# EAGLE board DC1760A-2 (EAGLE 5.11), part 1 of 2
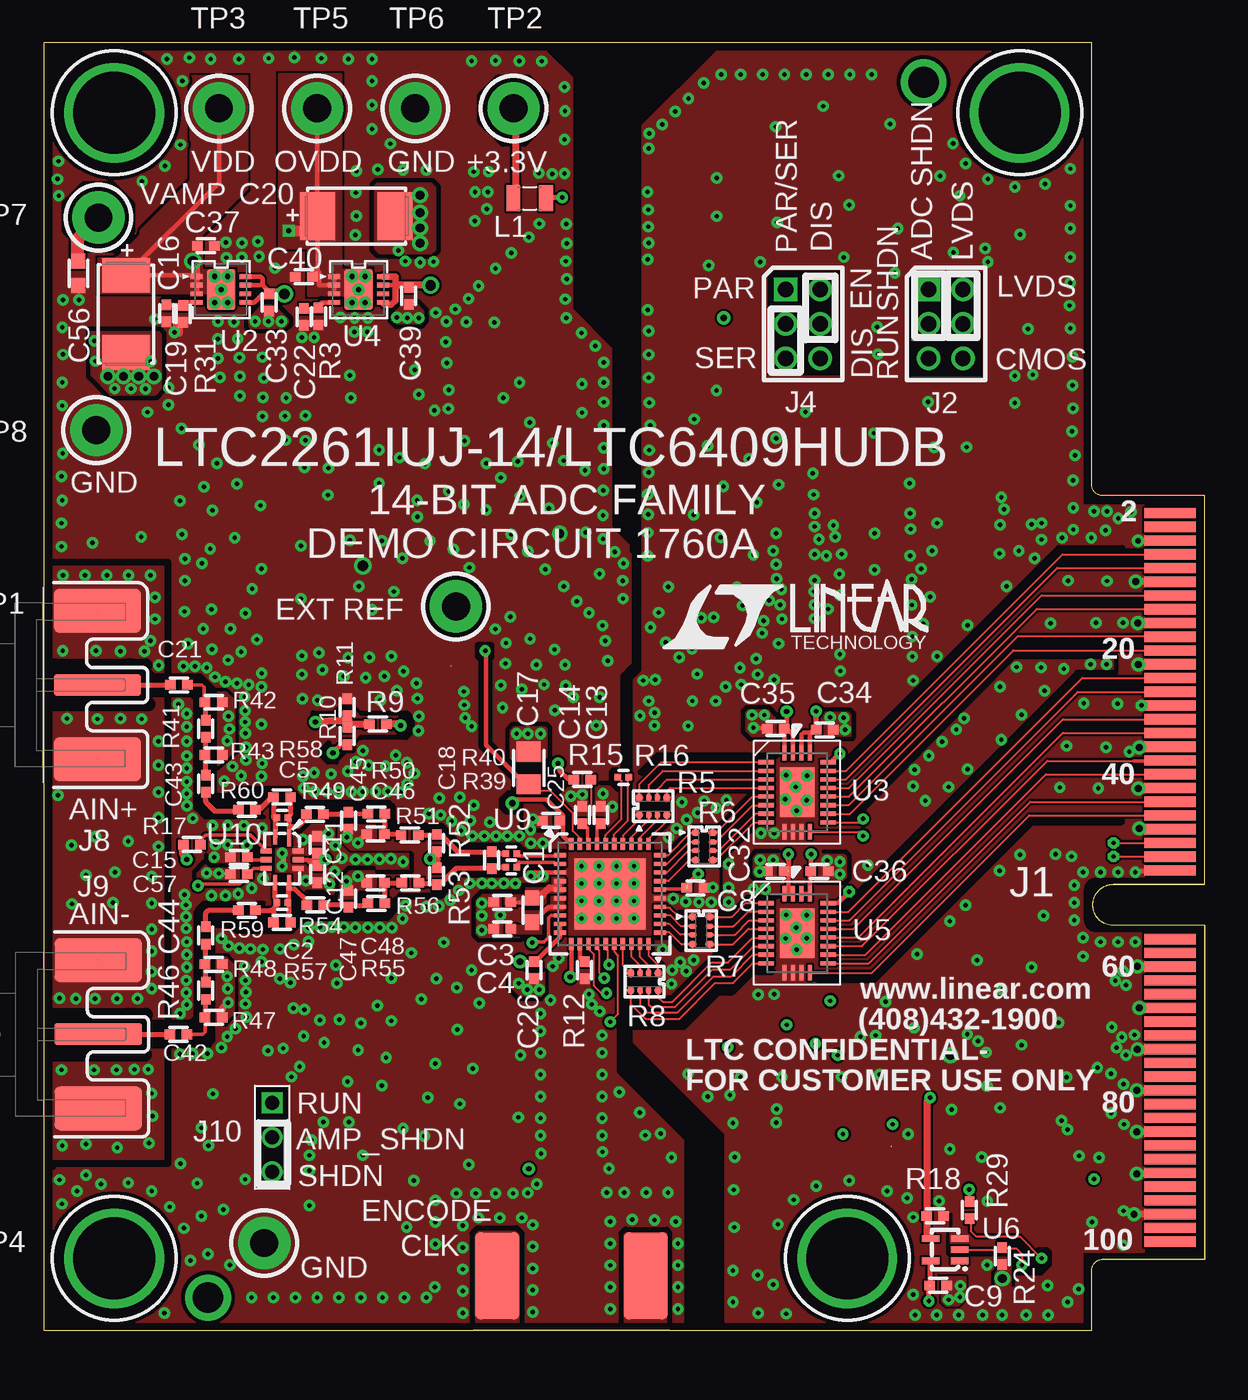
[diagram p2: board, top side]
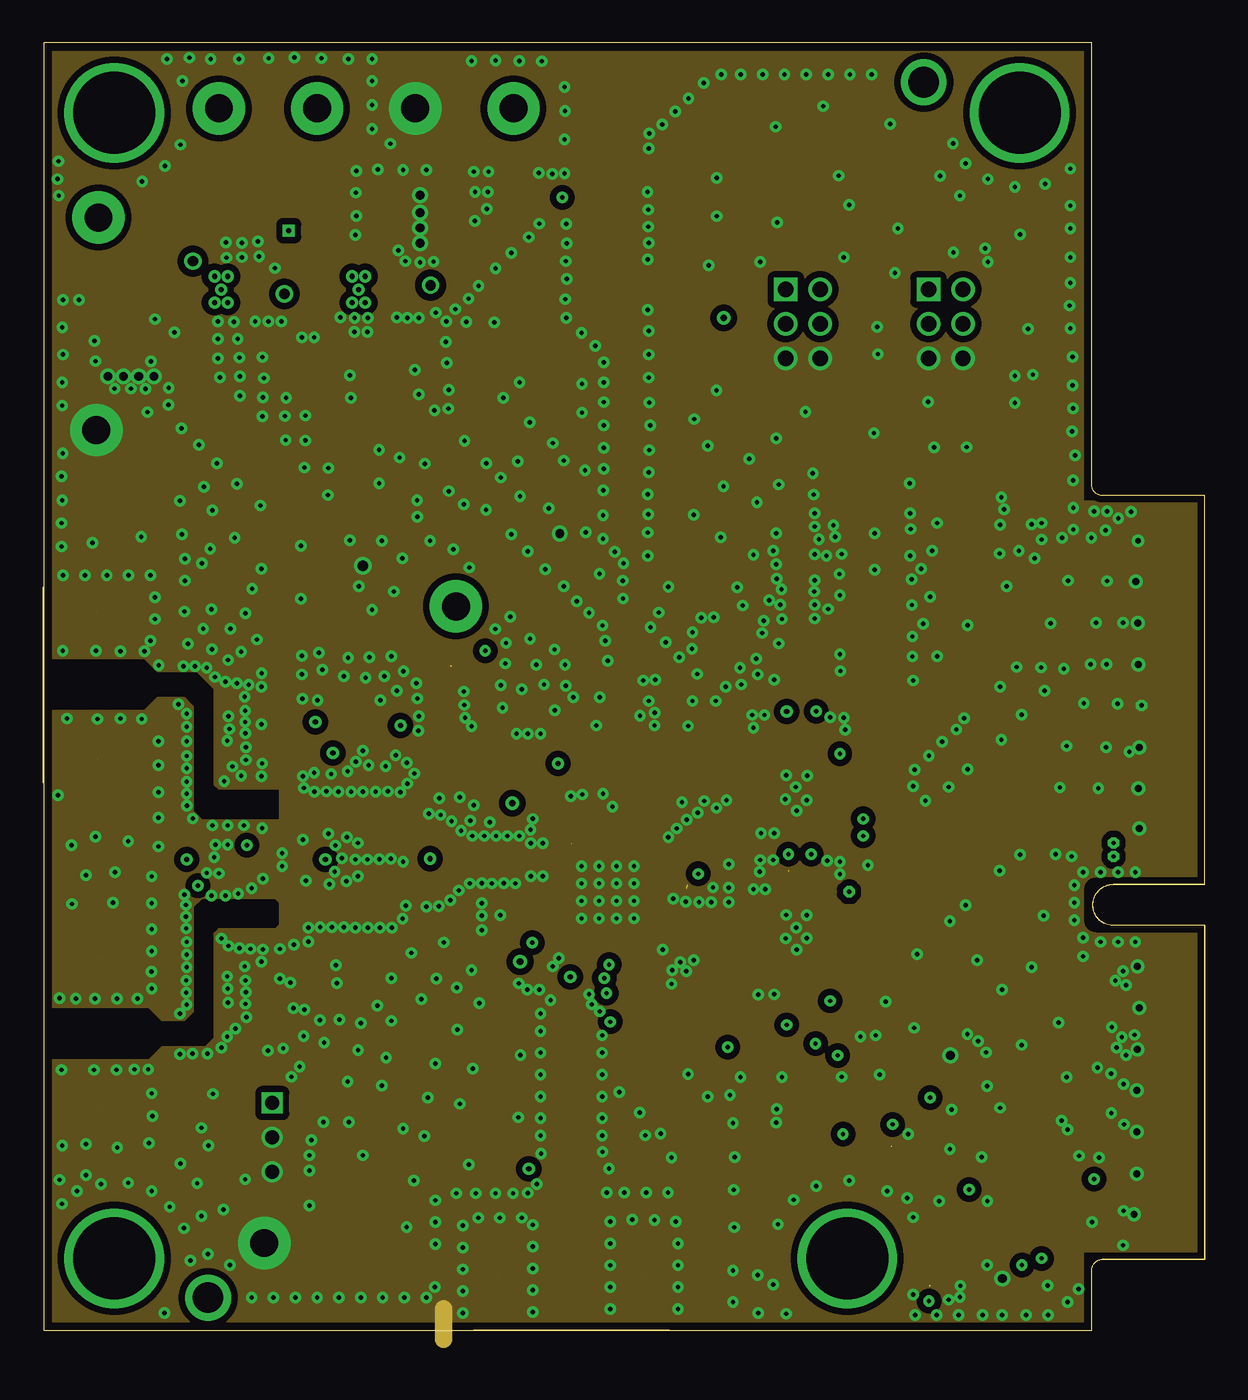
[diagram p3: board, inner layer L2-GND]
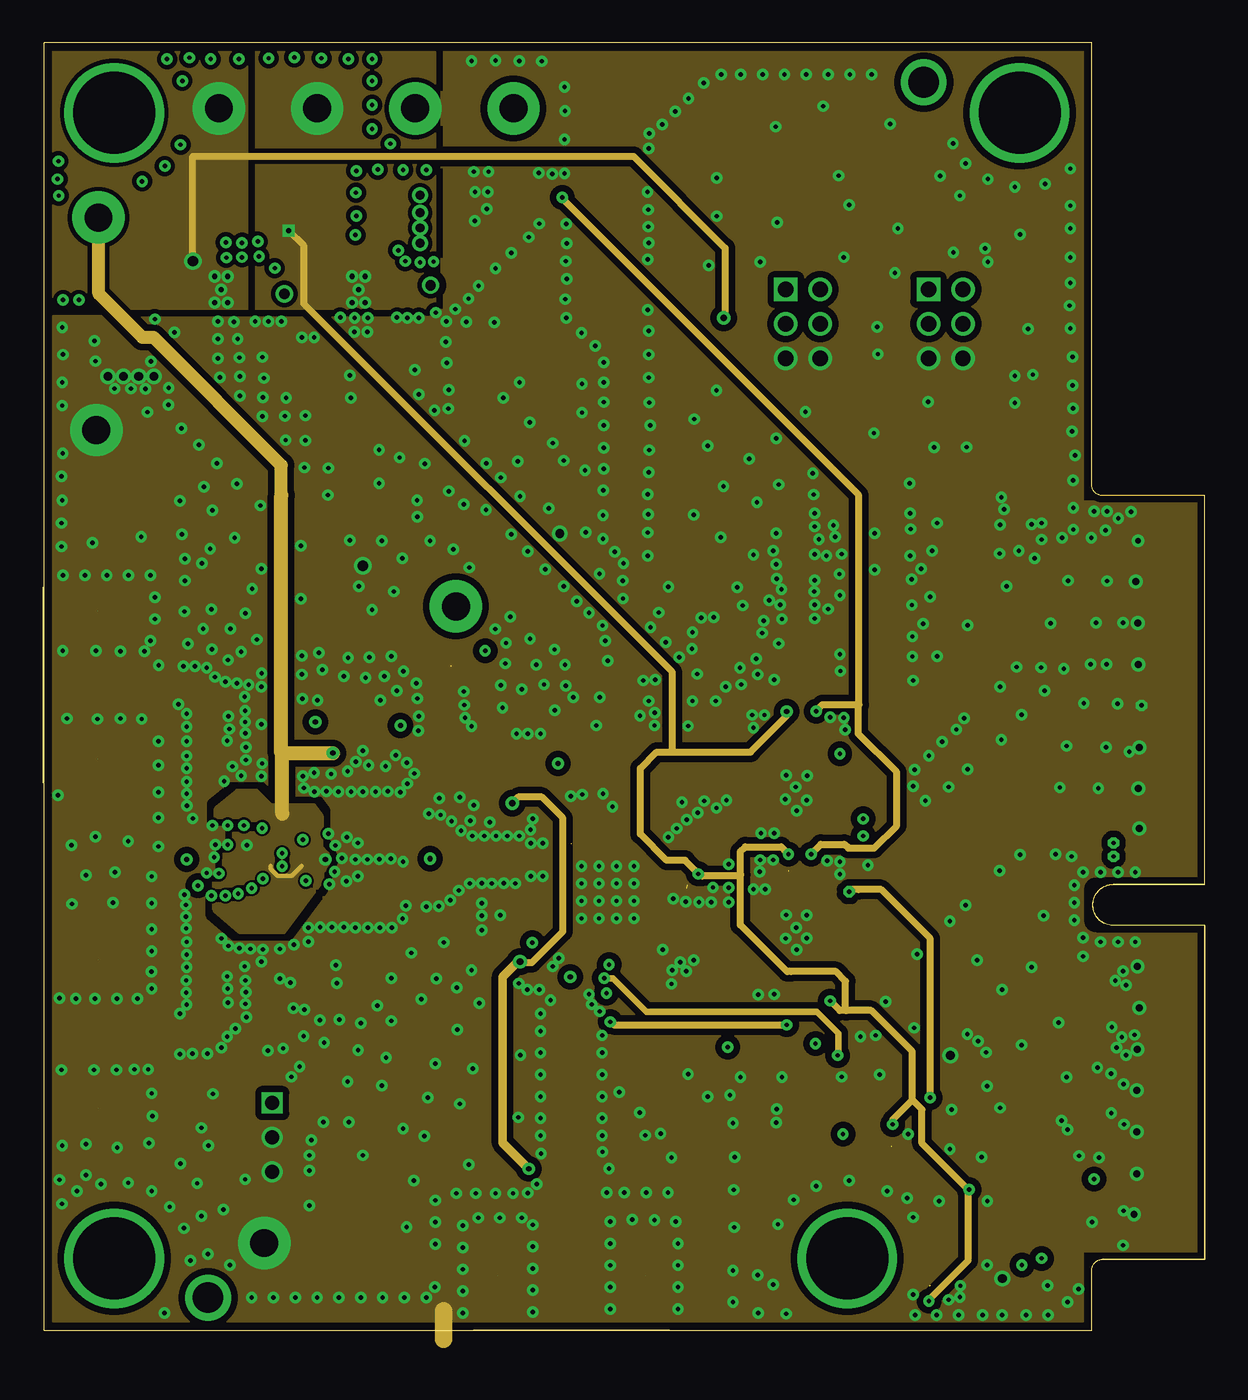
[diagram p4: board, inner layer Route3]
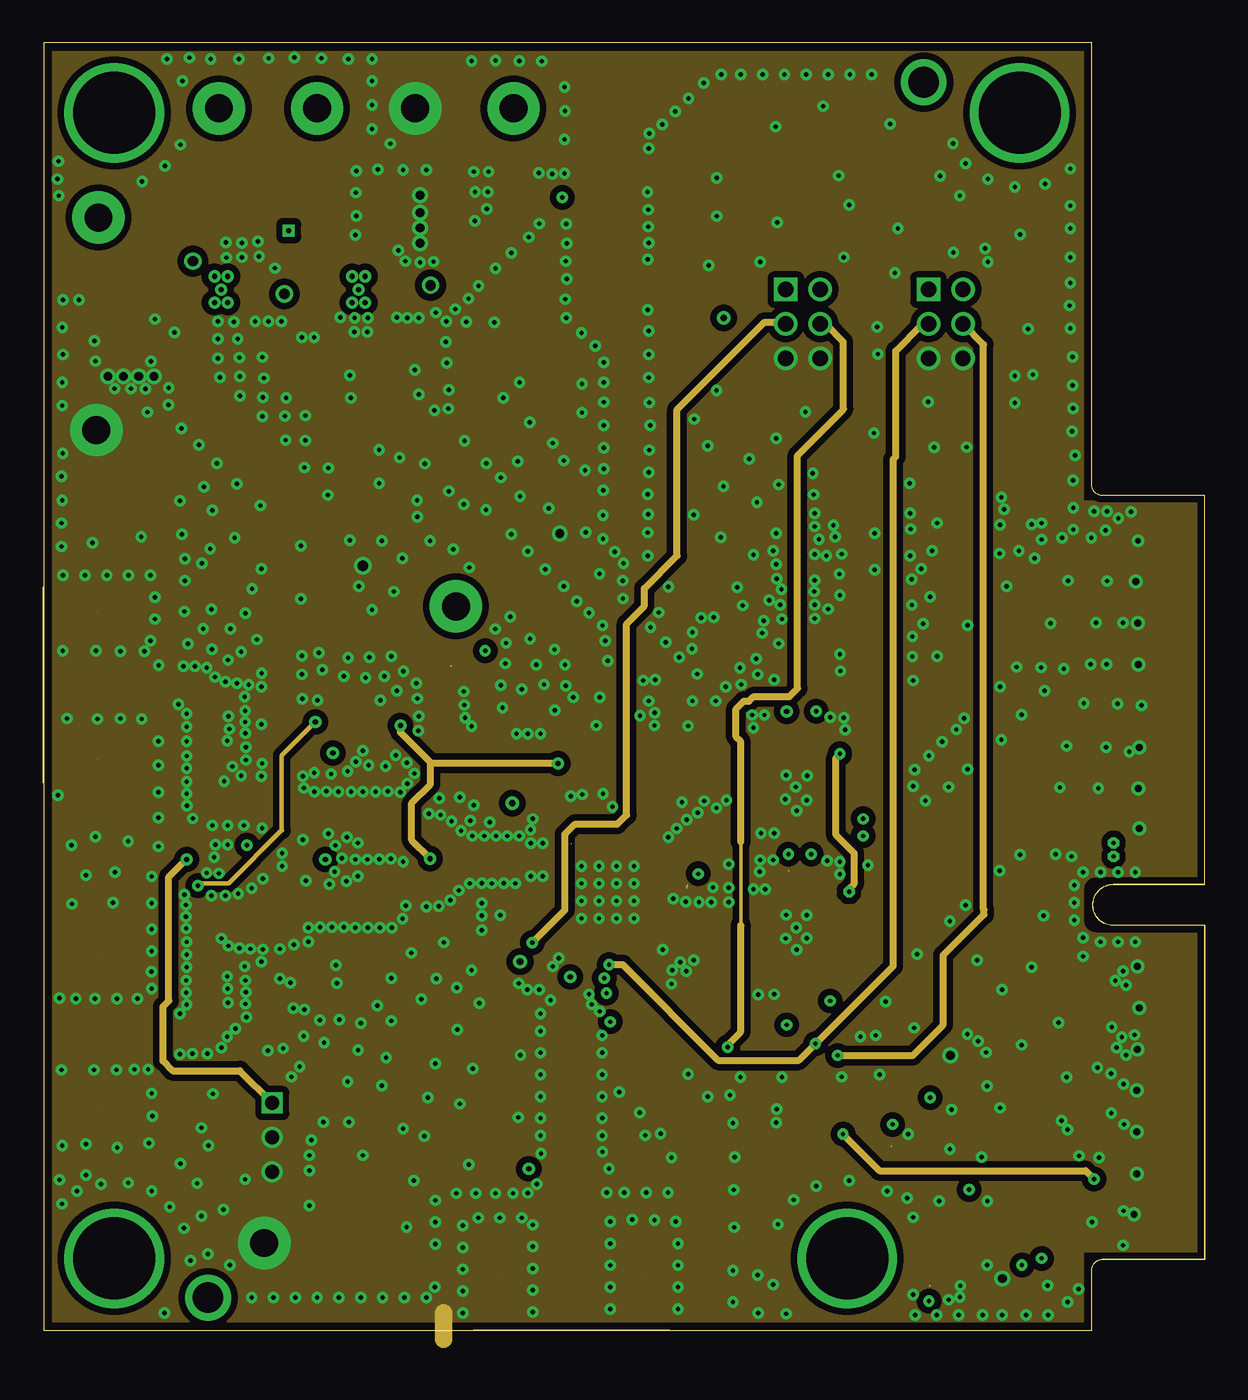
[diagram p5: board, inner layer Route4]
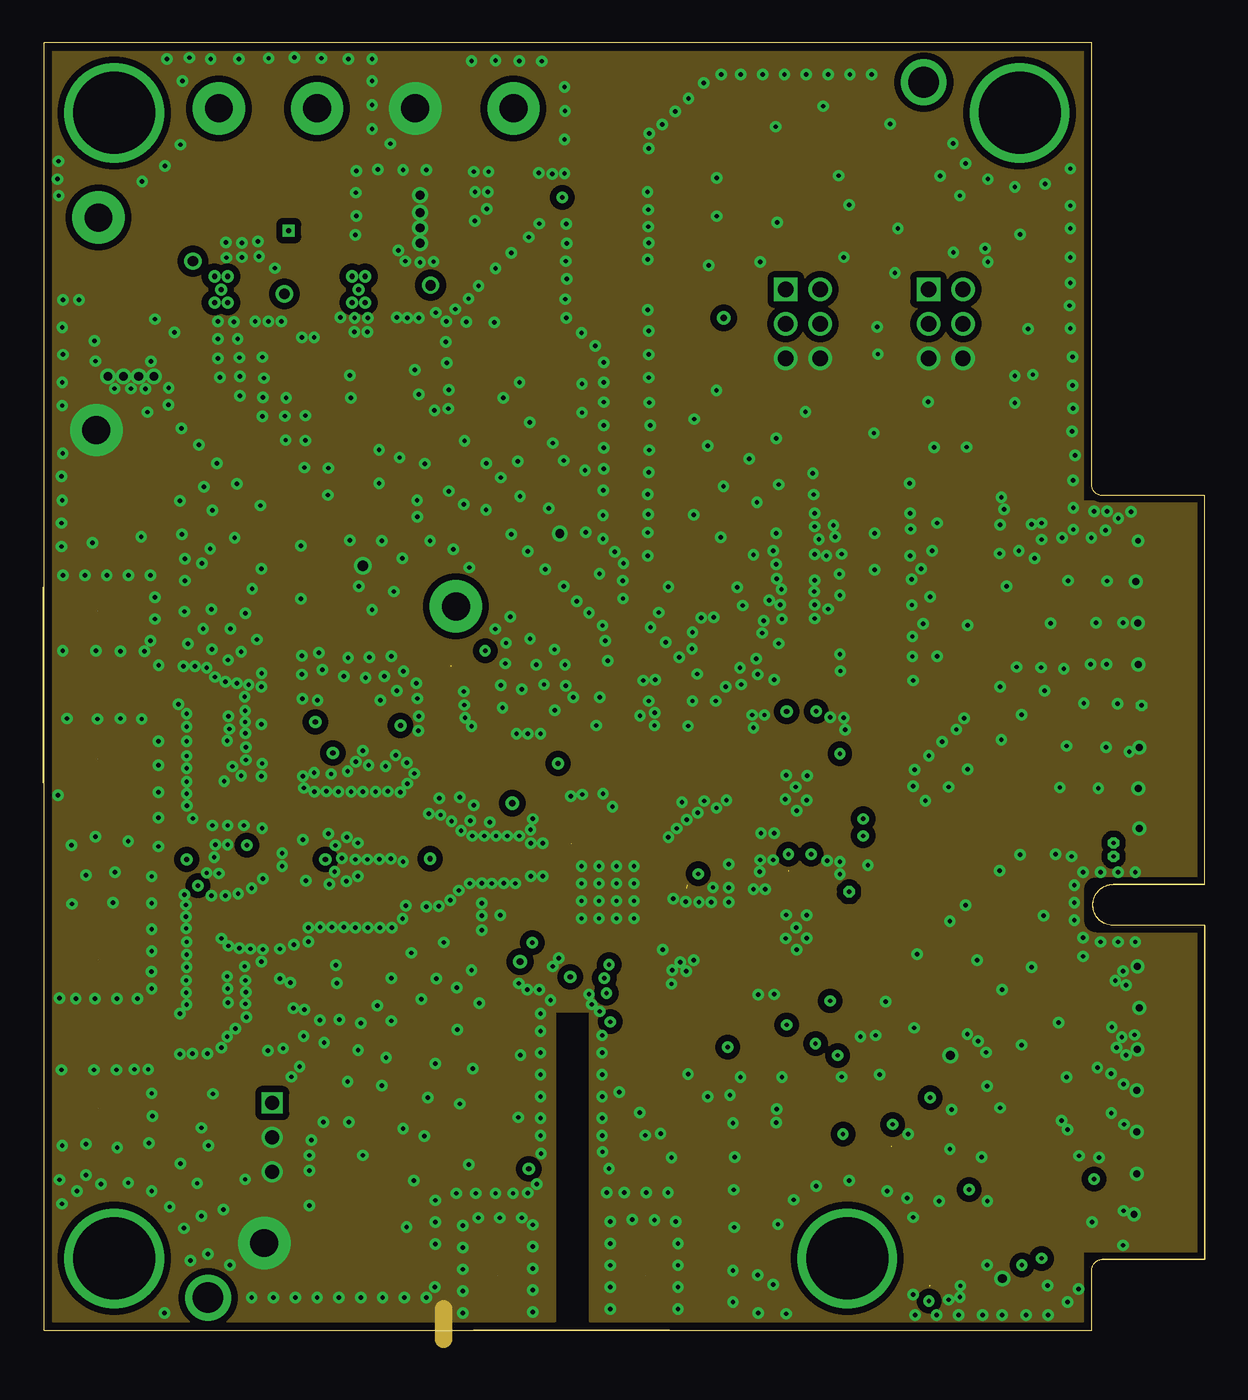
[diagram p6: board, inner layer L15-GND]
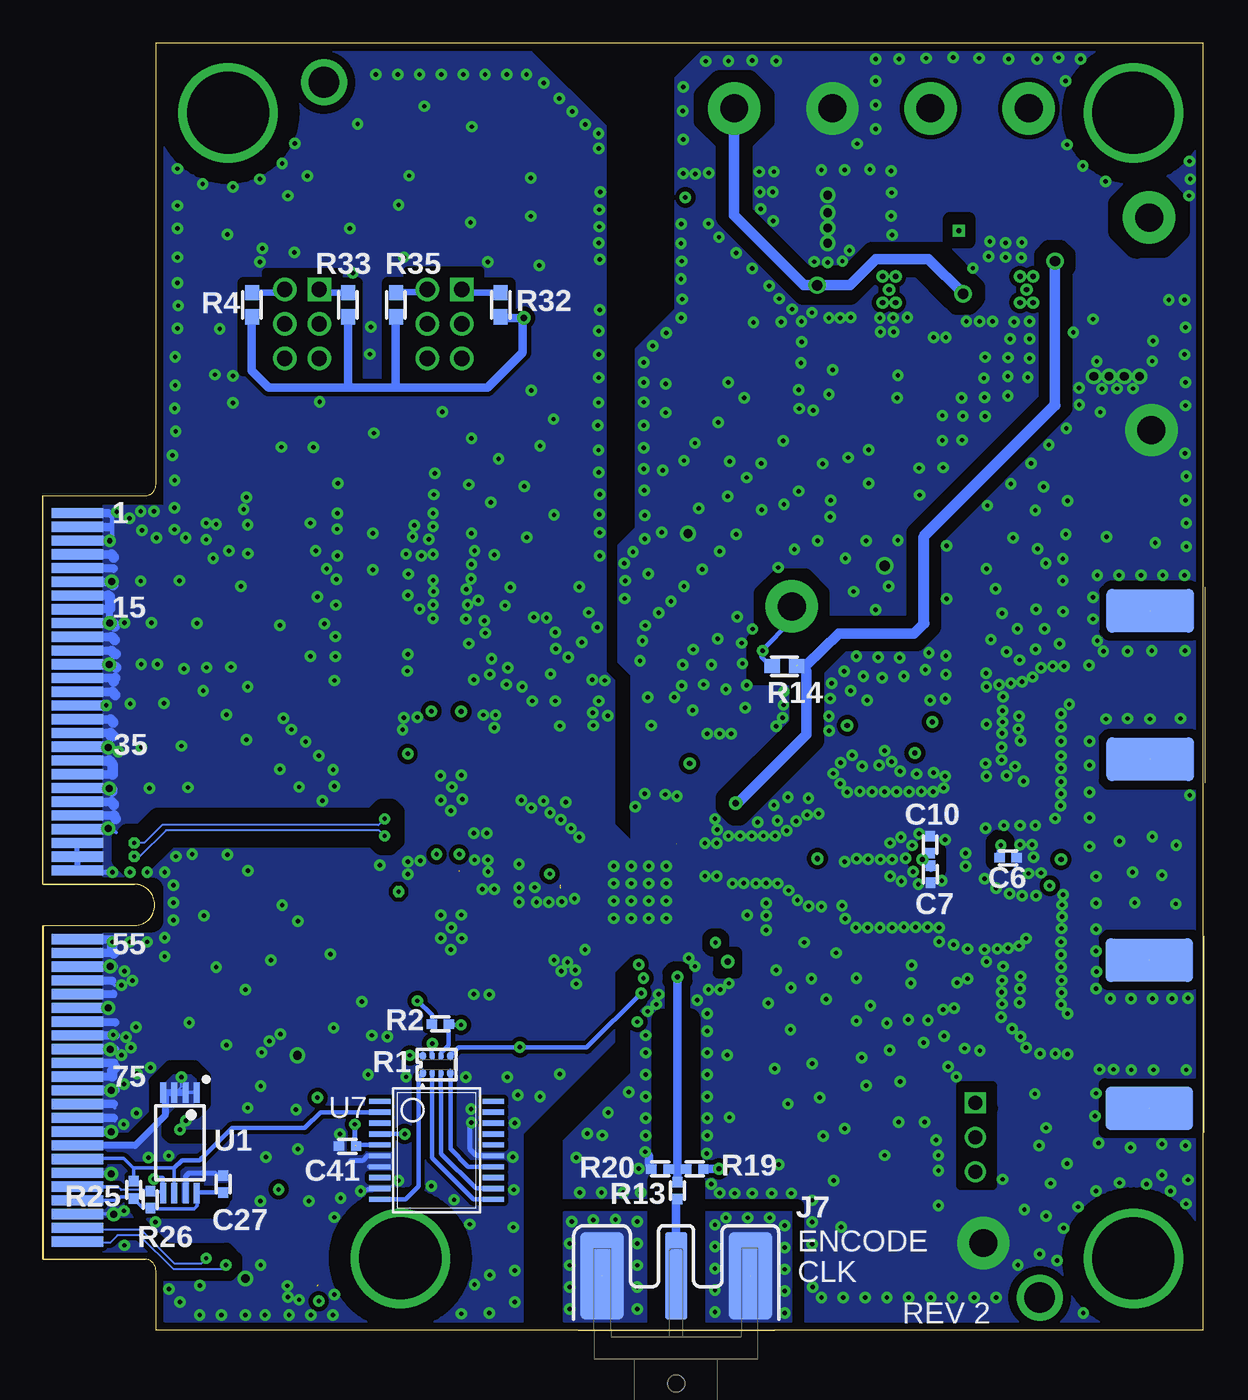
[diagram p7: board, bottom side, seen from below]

Size 67.62 x 74.93 mm. Coordinates in mm from the lower left corner, seen from the top.
Outline: 61.04,0 0.08,0 0.08,74.93 61.04,74.93 61.04,49.22 arc90 61.67,48.59 67.62,48.59 67.62,25.96 62.29,25.96 arc90 61.12,24.79 61.12,24.73 arc90 62.27,23.57 67.62,23.57 67.62,4.14 61.71,4.14 arc90 61.04,3.48 61.04,0
Copper layers (1*2+3*4+15*16): Top 0.0508mm / dielectric 0.4318mm / L2-GND 0.0254mm / dielectric 0.7112mm / Route3 0.0254mm / dielectric 0.3048mm / Route4 0.0254mm / dielectric 0.7112mm / L15-GND 0.0254mm / dielectric 0.4318mm / Bottom 0.0508mm
Design rules "Kim-Design Rules": minimum track width 5mil, minimum drill 10mil, track to track 5mil, track to pad 5mil, pad to pad 5mil, via to via 5mil, smd to smd 0mil, copper to edge 10mil, drill to drill 10mil, minimum pad ring 8mil, minimum via ring 8mil, stop-mask expansion 4mil, vias tented up to drill 15mil, thermal gap 10mil
Holes 0.25 mm at 121.98,32.81
Holes 0.3 mm at 121.98,37.89
Holes 0.38 mm at 121.98,42.97
Holes 0.41 mm at 121.98,48.05
Holes 0.51 mm at 121.98,53.13
Holes 0.61 mm at 121.98,58.21
Holes 0.81 mm at 121.98,63.29
Holes 0.89 mm at 121.98,68.37
Holes 1.63 mm at 121.98,73.45
Holes 1.78 mm at 121.98,78.53
Holes 4.78 mm at 121.98,83.61
tRestrict: area 12.3,8.4 to 14.2,14.2; area 50.4,55.5 to 54.7,61.6; area 42.2,55.6 to 46.4,61.7; area 8.2,0.5 to 11,3.3; area 49.8,71.2 to 52.7,74.1; 341 lines
bRestrict: area 12.3,8.4 to 14.2,14.2; area 42.2,55.6 to 46.4,61.7; area 50.4,55.5 to 54.6,61.6; area 8.2,0.5 to 11,3.3; area 49.8,71.2 to 52.7,74.1; 221 lines

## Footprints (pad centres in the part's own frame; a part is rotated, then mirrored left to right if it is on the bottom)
0603 = smd 0.889 x 0.813: 1 -0.71,0; 2 0.71,0
0201 = smd 0.381 x 0.381: 1 -0.32,0; 2 0.32,0
0402 = smd 0.61 x 0.559: 1 -0.498,0; 2 0.498,0
EIA6032-28(C) = smd 2.032 x 2.794: A -2.246,0; K 2.246,0
0805 = smd 1.143 x 1.397: 1 -0.952,0; 2 0.952,0
MEC8-150-02-L-D-EDGE_CONN-NEW-ORIGIN = smd 3 x 0.6 bottom: 1 3.3,22.8; 3 3.3,22; 5 3.3,21.2; 7 3.3,20.4; 9 3.3,19.6; 11 3.3,18.8; 13 3.3,18; 15 3.3,17.2; 17 3.3,16.4; 19 3.3,15.6; 21 3.3,14.8; 23 3.3,14; 25 3.3,13.2; 27 3.3,12.4; 29 3.3,11.6; 31 3.3,10.8; 33 3.3,10; 35 3.3,9.2; 37 3.3,8.4; 39 3.3,7.6; 41 3.3,6.8; 43 3.3,6; 45 3.3,5.2; 47 3.3,4.4; 49 3.3,3.6; 51 3.3,2.8; 53 3.3,2; 55 3.3,-2; 57 3.3,-2.8; 59 3.3,-3.6; 61 3.3,-4.4; 63 3.3,-5.2; 65 3.3,-6; 67 3.3,-6.8; 69 3.3,-7.6; 71 3.3,-8.4; 73 3.3,-9.2; 75 3.3,-10; 77 3.3,-10.8; 79 3.3,-11.6; 81 3.3,-12.4; 83 3.3,-13.2; 85 3.3,-14; 87 3.3,-14.8; 89 3.3,-15.6; 91 3.3,-16.4; 93 3.3,-17.2; 95 3.3,-18; 97 3.3,-18.8; 99 3.3,-19.6 | smd 3 x 0.6: 2 3.3,22.8; 4 3.3,22; 6 3.3,21.2; 8 3.3,20.4; 10 3.3,19.6; 12 3.3,18.8; 14 3.3,18; 16 3.3,17.2; 18 3.3,16.4; 20 3.3,15.6; 22 3.3,14.8; 24 3.3,14; 26 3.3,13.2; 28 3.3,12.4; 30 3.3,11.6; 32 3.3,10.8; 34 3.3,10; 36 3.3,9.2; 38 3.3,8.4; 40 3.3,7.6; 42 3.3,6.8; 44 3.3,6; 46 3.3,5.2; 48 3.3,4.4; 50 3.3,3.6; 52 3.3,2.8; 54 3.3,2; 56 3.3,-2; 58 3.3,-2.8; 60 3.3,-3.6; 62 3.3,-4.4; 64 3.3,-5.2; 66 3.3,-6; 68 3.3,-6.8; 70 3.3,-7.6; 72 3.3,-8.4; 74 3.3,-9.2; 76 3.3,-10; 78 3.3,-10.8; 80 3.3,-11.6; 82 3.3,-12.4; 84 3.3,-13.2; 86 3.3,-14; 88 3.3,-14.8; 90 3.3,-15.6; 92 3.3,-16.4; 94 3.3,-17.2; 96 3.3,-18; 98 3.3,-18.8; 100 3.3,-19.6
HD2X3-079 = drill 0.889 pad 1.372 square: 1 0,0 | drill 0.889 pad 1.372 round: 2 0,2.007; 3 2.007,0; 4 2.007,2.007; 5 4.013,0; 6 4.013,2.007
SMA-EDGE-MNT@2 = smd 5.08 x 1.27: 1 3.175,0 | smd 5.08 x 2.54: 2 3.175,4.318; 3 3.175,-4.318 | smd 5.08 x 2.54 bottom: 4 3.175,4.318; 5 3.175,-4.318
HDR-3X1PS-2MM = drill 0.813 square: 1 0,0 | drill 0.813 round: 2 2,0; 3 4,0
R0805 = smd 0.8 x 1.5: 1 -0.951,0; 2 0.951,0
MTG-8831 = drill 4.775 pad 4.775 round: 1 0,0
MNR04-QUAD-RES-ARRAY = smd 0.4 x 0.5: 1 -0.8,-0.5; 4 0.8,-0.5; 5 0.8,0.5; 8 -0.8,0.5 | smd 0.3 x 0.5: 2 -0.25,-0.5; 3 0.25,-0.5; 6 0.25,0.5; 7 -0.25,0.5
MILLMAX-2308-2 = drill 1.626 pad 3.048 round: 1 0,0
TSSOP8@1 = smd 0.35 x 1.2: 1 -0.975,-2.925; 2 -0.325,-2.925; 3 0.325,-2.925; 4 0.975,-2.925; 5 0.975,2.925; 6 0.325,2.925; 7 -0.325,2.925; 8 -0.975,2.925
DFN-8_3X3MM@1 = smd 0.28 x 0.675: 1 -0.75,-1.425; 2 -0.25,-1.425; 3 0.25,-1.425; 4 0.75,-1.425; 5 0.75,1.425; 6 0.25,1.425; 7 -0.25,1.425; 8 -0.75,1.425 | smd 2.38 x 1.65: USM 0,0
DFN_8X4 = smd 0.9 x 0.24: 1 -2.3,-0.25; 2 -2.3,-0.75; 11 2.3,-0.75; 12 2.3,-0.25; 13 2.3,0.25; 14 2.3,0.75; 23 -2.3,0.75; 24 -2.3,0.25 | smd 0.24 x 0.9: 3 -1.75,-1.8; 4 -1.25,-1.8; 5 -0.75,-1.8; 6 -0.25,-1.8; 7 0.25,-1.8; 8 0.75,-1.8; 9 1.25,-1.8; 10 1.75,-1.8; 15 1.75,1.8; 16 1.25,1.8; 17 0.75,1.8; 18 0.25,1.8; 19 -0.25,1.8; 20 -0.75,1.8; 21 -1.25,1.8; 22 -1.75,1.8 | smd 2.9 x 2: GP 0,0
SC70-5 = smd 0.381 x 1.016: 1 -0.65,-0.85; 2 0,-0.85; 3 0.65,-0.85; 4 0.65,0.85; 5 -0.65,0.85
SSOP20 = smd 0.305 x 1.245: 1 -2.794,-3.353; 2 -2.159,-3.353; 3 -1.524,-3.353; 4 -0.889,-3.353; 5 -0.254,-3.353; 6 0.381,-3.353; 7 1.016,-3.353; 8 1.651,-3.353; 9 2.286,-3.353; 10 2.921,-3.353; 11 2.921,3.251; 12 2.286,3.251; 13 1.651,3.251; 14 1.016,3.251; 15 0.381,3.251; 16 -0.254,3.251; 17 -0.889,3.251; 18 -1.524,3.251; 19 -2.159,3.251; 20 -2.794,3.251
TQFN_6X6_40PIN = smd 0.7 x 0.25: 1 -2.9,2.25; 2 -2.9,1.75; 3 -2.9,1.25; 4 -2.9,0.75; 5 -2.9,0.25; 6 -2.9,-0.25; 7 -2.9,-0.75; 8 -2.9,-1.25; 9 -2.9,-1.75; 10 -2.9,-2.25; 21 2.9,-2.25; 22 2.9,-1.75; 23 2.9,-1.25; 24 2.9,-0.75; 25 2.9,-0.25; 26 2.9,0.25; 27 2.9,0.75; 28 2.9,1.25; 29 2.9,1.75; 30 2.9,2.25 | smd 0.25 x 0.7: 11 -2.25,-2.9; 12 -1.75,-2.9; 13 -1.25,-2.9; 14 -0.75,-2.9; 15 -0.25,-2.9; 16 0.25,-2.9; 17 0.75,-2.9; 18 1.25,-2.9; 19 1.75,-2.9; 20 2.25,-2.9; 31 2.25,2.9; 32 1.75,2.9; 33 1.25,2.9; 34 0.75,2.9; 35 0.25,2.9; 36 -0.25,2.9; 37 -0.75,2.9; 38 -1.25,2.9; 39 -1.75,2.9; 40 -2.25,2.9 | smd 4.15 x 4.15: EP 0,0
TQFN_3MM_X_2MM = smd 0.95 x 0.25: P1 -1.275,0.4 | smd 0.85 x 0.25: P2 -1.325,-0.4; P6 1.325,-0.4; P7 1.325,0.4 | smd 0.25 x 0.65: P3 -0.5,-0.925; P4 0,-0.925; P5 0.5,-0.925; P8 0.5,0.925; P9 0,0.925; P10 -0.5,0.925 | smd 0.9 x 0.25: PAD 0,0.075
TOOLINGHOLE = drill 1.778 pad 1.778 round: 1 0,0

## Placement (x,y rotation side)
C1  2.2uF  [0603]  28.48,24.46 270 top
C2  0.8pF  [0201]  13.93,24.89 0 top
C3  0.1uF  [0402]  26.73,24.92 0 top
C4  0.1uF  [0402]  26.73,23.37 0 top
C5  0.8pF  [0201]  13.93,29.85 0 top
C6  0.1uF  [0402]  11.44,27.51 0 bottom
C7  0.1uF  [0402]  15.96,26.54 270 bottom
C8  0.1uF  [0402]  37.98,25.76 0 top
C9  0.1uF  [0402]  52.1,2.62 0 top
C10  0.1uF  [0402]  15.98,28.27 90 bottom
C11  1000pF  [0402]  15.96,28.27 90 top
C12  1000pF  [0402]  15.98,26.54 270 top
C13  1.0uF  [0402]  32.47,30 90 top
C14  1.0uF  [0402]  31.4,30 270 top
C15  1000pF  [0402]  11.41,27.53 180 top
C16  100uF  [EIA6032-28(C)]  4.83,59.16 270 top
C17  2.2uF  [0805]  28.28,32.74 90 top
C18  OPT  [0402]  26.12,27.38 90 top
C19  0.1uF  [0402]  7.19,59.18 270 top
C20  100uF  [EIA6032-28(C)]  18.24,64.85 0 top
C21  0.1uF  [0402]  7.91,37.57 0 top
C22  0.1uF  [0402]  15.2,58.98 270 top
C25  0.1uF  [0402]  29.57,29.67 0 top
C26  0.1uF  [0402]  28.58,20.96 90 top
C27  0.1uF  [0402]  57.13,8.51 90 bottom
C32  0.1uF  [0402]  42.65,26.72 180 top
C33  1.0uF  [0402]  13.16,59.82 90 top
C34  0.1uF  [0402]  45.5,34.95 0 top
C35  0.1uF  [0402]  42.65,35.03 180 top
C36  0.1uF  [0402]  45.19,26.72 0 top
C37  1.0uF  [0402]  9.48,63.12 180 top
C39  1.0uF  [0402]  21.29,60.2 90 top
C40  1.0uF  [0402]  15.2,61.32 0 top
C41  0.1uF  [0402]  49.89,10.72 180 bottom
C42  TBD  [0402]  7.88,17.23 0 top
C43  0.1uF  [0402]  9.48,31.81 270 top
C44  0.1uF  [0402]  9.48,22.99 90 top
C45  OPT  [0402]  17.79,29.67 90 top
C46  OPT  [0402]  19.36,28.88 0 top
C47  OPT  [0402]  17.79,25.13 270 top
C48  OPT  [0402]  19.36,26.05 0 top
C56  2.2uF  [0603]  2.06,61.52 90 top
C57  0.1uF  [0402]  11.41,26.54 180 top
J1  MEC8-150-02-L-D-EDGE_CONNRE-DIM  [MEC8-150-02-L-D-EDGE_CONN-NEW-ORIGIN]  62.31,24.77 0 top
J2  HD2X3-079  [HD2X3-079]  51.54,60.58 270 top
J4  HD2X3-079  [HD2X3-079]  43.24,60.58 270 top
J7  [SMA-EDGE-MNT@2]  30.77,0 90 bottom
J8  [SMA-EDGE-MNT@2]  0,37.56 0 top
J9  [SMA-EDGE-MNT@2]  0.05,17.23 0 top
J10  HD1X3-079  [HDR-3X1PS-2MM]  13.34,13.23 270 top
L1  BEAD  [R0805]  28.33,65.89 0 top
MH1  MTG-8831-STANDOFF  [MTG-8831]  4.15,70.87 0 top
MH2  MTG-8831-STANDOFF  [MTG-8831]  56.85,70.87 0 top
MH3  MTG-8831-STANDOFF  [MTG-8831]  4.15,4.19 0 top
MH4  MTG-8831-STANDOFF  [MTG-8831]  46.82,4.19 0 top
R1  33  [MNR04-QUAD-RES-ARRAY]  44.71,15.47 0 bottom
R2  10k  [0402]  44.48,17.83 0 bottom
R3  180k  [0402]  16.03,59 270 top
R4  1k  [0603]  55.45,59.69 270 bottom
R5  33  [MNR04-QUAD-RES-ARRAY]  35.52,30.51 0 top
R6  33  [MNR04-QUAD-RES-ARRAY]  38.49,28.17 270 top
R7  33  [MNR04-QUAD-RES-ARRAY]  38.31,23.27 270 top
R8  33  [MNR04-QUAD-RES-ARRAY]  35.01,20.29 180 top
R9  0  [0402]  19.49,35.28 0 top
R10  TBD  [0402]  17.71,34.59 90 top
R11  TBD  [0402]  17.71,36.27 90 top
R12  0  [0402]  31.53,20.96 270 top
R13  0  [0402]  30.69,8.13 270 bottom
R14  1k  [0603]  24.47,38.66 0 bottom
R15  100  [0402]  31.4,32.05 180 top
R16  100  [0201]  33.79,32.18 0 top
R17  10  [0402]  8.67,28.27 0 top
R18  OPT  [0402]  51.92,6.65 180 top
R19  OPT  [0402]  29.67,9.4 180 bottom
R20  OPT  [0402]  31.71,9.4 180 bottom
R24  100k  [0402]  55.84,4.32 90 top
R25  4.99k  [0402]  62.34,8.18 270 bottom
R26  4.99k  [0402]  61.37,7.62 270 bottom
R29  4.99k  [0402]  53.93,7.01 90 top
R31  180k  [0402]  8.16,59.16 270 top
R32  1k  [0603]  40.98,59.69 270 bottom
R33  1k  [0603]  49.87,59.69 270 bottom
R35  1k  [0603]  47.07,59.69 270 bottom
R39  10  [0201]  27.26,26.96 0 top
R40  10  [0201]  27.26,27.74 0 top
R41  0  [0402]  9.48,35.02 270 top
R42  TBD  [0402]  9.94,36.56 0 top
R43  66.5  [0402]  9.94,33.49 0 top
R46  TBD  [0402]  9.48,19.76 90 top
R47  TBD  [0402]  9.94,18.22 0 top
R48  0  [0402]  9.94,21.31 0 top
R49  30.1  [0402]  15.83,30.04 180 top
R50  0  [0402]  19.41,30.07 180 top
R51  0  [0402]  21.34,28.83 180 top
R52  TBD  [0402]  22.92,28.37 270 top
R53  TBD  [0402]  22.92,26.44 270 top
R54  30.1  [0402]  15.85,24.75 180 top
R55  0  [0402]  19.41,24.86 180 top
R56  0  [0402]  21.39,26.05 180 top
R57  150  [0402]  13.92,23.74 180 top
R58  150  [0402]  13.92,31.04 0 top
R59  150  [0402]  11.87,24.45 0 top
R60  150  [0402]  11.87,30.3 0 top
TP1  TURRET-064  [MILLMAX-2308-2]  24.03,42.14 0 top
TP2  TURRET-064  [MILLMAX-2308-2]  27.39,71.12 0 top
TP3  TURRET-064  [MILLMAX-2308-2]  10.24,71.12 90 top
TP4  TURRET-064  [MILLMAX-2308-2]  12.88,5.08 90 top
TP5  TURRET-064  [MILLMAX-2308-2]  15.96,71.12 90 top
TP6  TURRET-064  [MILLMAX-2308-2]  21.67,71.12 0 top
TP7  TURRET-064  [MILLMAX-2308-2]  3.23,64.77 0 top
TP8  TURRET-064  [MILLMAX-2308-2]  3.11,52.4 0 top
U1  24LC02-I/ST  [TSSOP8@1]  59.65,10.92 180 bottom
U2  LT3080EDD  [DFN-8_3X3MM@1]  10.37,60.58 270 top
U3  FXLH42245  [DFN_8X4]  43.9,31.32 270 top
U4  LT3080EDD  [DFN-8_3X3MM@1]  18.37,60.58 270 top
U5  FXLH42245  [DFN_8X4]  43.9,23.11 270 top
U6  NC7SP14P5X  [SC70-5]  52.51,4.7 90 top
U7  PCF8574ATS  [SSOP20]  44.66,10.54 270 bottom
U9  LTC2261IUJ-14  [TQFN_6X6_40PIN]  33,25.4 0 top
U10  LTC6409HUDB  [TQFN_3MM_X_2MM]  13.92,27.39 270 top
U$3  [TITLEBLK-REV]  not placed on the board
U$8  [6-LAYER-NAME]  -1.19,-1.27 0 top
U$9  [TITLEBLK-REV-ASSYB]  not placed on the board
U$10  [LTC-LOGO]  35.39,39.37 0 top
U$13  [STACKUP-6LAYER]  not placed on the board
X1  TOOLINGHOLE-70MIL  [TOOLINGHOLE]  51.26,72.64 0 top
X2  TOOLINGHOLE-70MIL  [TOOLINGHOLE]  9.61,1.91 0 top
